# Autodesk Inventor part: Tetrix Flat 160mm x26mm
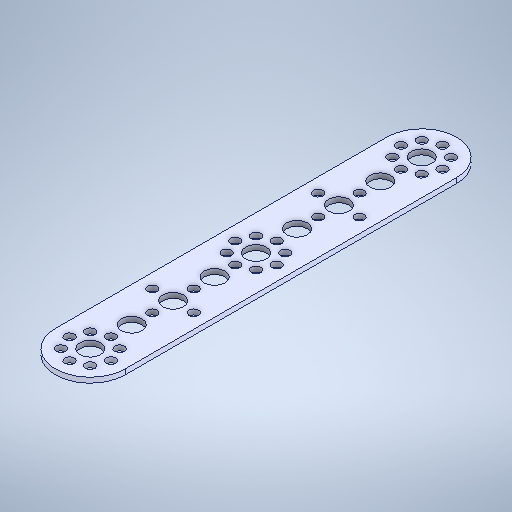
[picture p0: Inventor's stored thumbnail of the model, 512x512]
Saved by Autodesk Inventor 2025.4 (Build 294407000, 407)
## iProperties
Created: 2021-10
Part Number: Tetrix Flat 160mm x26mm
Material: Genérico
Document SubType Name: Modeling
Designer: usuario
Density: 1 g/cm^3
Appearance: Valor por defecto
Author: usuario
Sending System: SolidWorks 2016
Last Author: LENOVO
Last Saved: 2021-10-23
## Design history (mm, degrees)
feature "Boss-Extrude1"
node "Plane1"
node "Sólido1"
